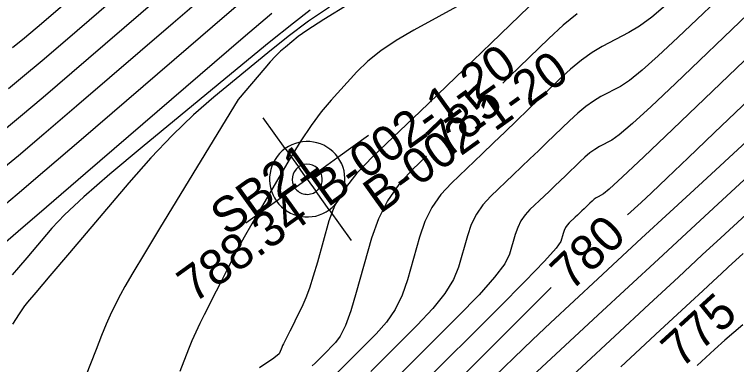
# Model space of a CAD drawing. Extents: x 2079879 to 2092887, y 778083 to 784051.
# Drawn here: x 2084271.8 to 2084329.3, y 781004.3 to 781032.2 of the extents above; entities that cross this region are included whole.
import ezdxf

# ---------------------------------------------------------------- set-up
doc = ezdxf.new("R2010")
doc.units = 0
for name, color, linetype in [('DT_X_Contour_Major', 7, 'Continuous'), ('DT_X_Contour_Minor', 7, 'Continuous'), ('GT_Instrumented_Soil_Boring', 7, 'Continuous'), ('GT_Project_Text', 7, 'Continuous'), ('SV_X_Text_Comment', 7, 'Continuous'), ('SV_X_Text_Elevation', 7, 'Continuous'), ('SV_X_Text_Name', 7, 'Continuous')]:
    doc.layers.add(name, color=color, linetype=linetype)

msp = doc.modelspace()

# ---------------------------------------------------------------- linework, layer by layer
at = {"layer": 'DT_X_Contour_Major'}
for points in [[(2084360.852, 781055.872), (2084359.712, 781054.727), (2084359.083, 781054.086), (2084358.088, 781053.046), (2084357.445, 781052.385), (2084356.264, 781051.182), (2084354.543, 781049.435), (2084352.284, 781047.146), (2084345.54, 781040.319), (2084343.285, 781038.038), (2084341.579, 781036.315), (2084340.42, 781035.151), (2084339.81, 781034.546), (2084338.913, 781033.675), (2084338.331, 781033.114), (2084337.258, 781032.085), (2084335.693, 781030.587), (2084333.638, 781028.621), (2084327.502, 781022.753), (2084325.413, 781020.757), (2084323.746, 781019.17), (2084322.501, 781017.992), (2084321.679, 781017.224), (2084320.608, 781016.237)], [(2084281.986, 781035.329), (2084276.04, 781030.211), (2084274.032, 781028.491), (2084272.466, 781027.169), (2084271.345, 781026.244)], [(2084295.339, 781032.514), (2084294.017, 781031.482), (2084292.089, 781029.927), (2084289.553, 781027.851), (2084281.982, 781021.617), (2084279.404, 781019.461), (2084277.35, 781017.67), (2084275.817, 781016.242), (2084274.808, 781015.179), (2084272.814, 781012.828), (2084272.148, 781012.049), (2084271.647, 781011.475)], [(2084316.594, 781032.221), (2084315.485, 781031.315), (2084314.336, 781030.258), (2084311.218, 781027.241), (2084310.668, 781026.71)], [(2084304.6, 781020.901), (2084303.469, 781019.823), (2084302.397, 781018.654), (2084301.502, 781017.356), (2084300.782, 781015.929), (2084300.238, 781014.374), (2084299.023, 781010.054), (2084298.577, 781008.59), (2084298.153, 781007.439), (2084297.749, 781006.599), (2084297.366, 781006.071), (2084296.372, 781005.08), (2084296.027, 781004.737), (2084295.736, 781004.45), (2084295.499, 781004.22)], [(2084314.526, 781010.444), (2084313.966, 781009.888), (2084311.739, 781007.669), (2084305.072, 781001.02)]]:
    msp.add_lwpolyline(points, dxfattribs=at)
at = {"layer": 'DT_X_Contour_Minor'}
for points in [[(2084329.18, 781034.706), (2084324.612, 781030.338), (2084323.041, 781028.866), (2084321.753, 781027.727), (2084320.748, 781026.921), (2084320.026, 781026.448), (2084318.479, 781025.631), (2084317.888, 781025.281), (2084317.272, 781024.846), (2084316.634, 781024.323), (2084315.972, 781023.715), (2084314.177, 781021.978), (2084313.504, 781021.328), (2084312.833, 781020.683), (2084312.163, 781020.041), (2084311.495, 781019.403), (2084309.715, 781017.706), (2084309.098, 781017.033), (2084308.582, 781016.286), (2084308.168, 781015.464), (2084307.855, 781014.569), (2084307.155, 781012.081), (2084306.752, 781011.093), (2084306.069, 781009.992), (2084305.106, 781008.78), (2084303.862, 781007.456), (2084300.172, 781003.775)], [(2084290.705, 781033.872), (2084288.536, 781032.006), (2084285.676, 781029.544), (2084277.124, 781022.185), (2084274.251, 781019.722), (2084272.042, 781017.85), (2084270.5, 781016.571)], [(2084287.054, 781033.717), (2084284.446, 781031.472), (2084276.763, 781024.861), (2084274.168, 781022.638), (2084272.146, 781020.929), (2084270.696, 781019.735)], [(2084283.216, 781033.4), (2084276.401, 781027.536), (2084274.1, 781025.565), (2084272.306, 781024.049), (2084271.02, 781022.99)], [(2084298.426, 781032.995), (2084296.434, 781031.76), (2084295.088, 781030.895), (2084294.389, 781030.4), (2084293.387, 781029.575), (2084293.002, 781029.238), (2084292.597, 781028.845), (2084292.174, 781028.396), (2084291.732, 781027.892), (2084289.624, 781025.407), (2084283.37, 781015.14), (2084282.17, 781013.161), (2084281.251, 781011.628), (2084280.613, 781010.538), (2084280.256, 781009.893), (2084279.678, 781008.764), (2084279.43, 781008.245), (2084279.12, 781007.534), (2084278.747, 781006.631), (2084278.312, 781005.537), (2084277.07, 781002.364)], [(2084307.579, 781033.102), (2084303.597, 781030.923), (2084302.194, 781030.102), (2084300.972, 781029.274), (2084299.931, 781028.439), (2084299.071, 781027.597), (2084297.019, 781025.343), (2084296.238, 781024.42), (2084295.435, 781023.344), (2084294.61, 781022.115), (2084293.763, 781020.731), (2084291.474, 781016.836), (2084290.701, 781015.514), (2084290.1, 781014.47), (2084289.67, 781013.703), (2084289.411, 781013.214), (2084288.95, 781012.281), (2084288.753, 781011.886), (2084288.51, 781011.403), (2084288.219, 781010.83), (2084287.881, 781010.169), (2084286.917, 781008.287), (2084286.568, 781007.587), (2084286.245, 781006.897), (2084285.947, 781006.217), (2084285.674, 781005.548), (2084284.981, 781003.777)], [(2084313.518, 781033.53), (2084309.738, 781029.873), (2084308.322, 781028.505), (2084306.909, 781027.146), (2084305.5, 781025.795), (2084304.093, 781024.452), (2084300.346, 781020.881), (2084299.073, 781019.556), (2084298.065, 781018.26), (2084297.323, 781016.992), (2084296.845, 781015.752), (2084295.926, 781012.483), (2084295.594, 781011.35), (2084295.289, 781010.403), (2084295.011, 781009.642), (2084294.759, 781009.066), (2084294.123, 781007.78), (2084293.905, 781007.339), (2084293.728, 781006.982), (2084293.591, 781006.709), (2084293.495, 781006.521), (2084293.295, 781006.129), (2084293.222, 781005.983), (2084293.155, 781005.839), (2084293.093, 781005.698), (2084293.036, 781005.558), (2084292.891, 781005.189), (2084292.469, 781004.838), (2084291.312, 781004.059)], [(2084275.678, 781032.887), (2084273.963, 781031.418), (2084272.627, 781030.289), (2084271.669, 781029.499)], [(2084296.883, 781032.755), (2084295.225, 781031.621), (2084293.588, 781030.411), (2084291.971, 781029.126), (2084287.684, 781025.596), (2084286.056, 781024.177), (2084284.387, 781022.566), (2084282.677, 781020.764), (2084280.925, 781018.771), (2084276.198, 781013.201), (2084274.647, 781011.372), (2084273.537, 781010.065), (2084272.869, 781009.28), (2084272.643, 781009.015), (2084272.628, 781009.005), (2084272.519, 781008.842), (2084272.201, 781008.358), (2084271.676, 781007.554)], [(2084323.614, 781032.875), (2084322.525, 781031.961), (2084321.554, 781031.245), (2084320.701, 781030.726), (2084318.584, 781029.608), (2084317.775, 781029.13), (2084316.933, 781028.533), (2084316.06, 781027.819), (2084315.154, 781026.987), (2084312.697, 781024.609), (2084311.777, 781023.721), (2084310.859, 781022.837), (2084309.942, 781021.959), (2084309.028, 781021.086), (2084306.592, 781018.765), (2084305.748, 781017.844), (2084305.042, 781016.821), (2084304.475, 781015.697), (2084304.047, 781014.471), (2084303.089, 781011.068), (2084302.665, 781009.841), (2084302.111, 781008.715), (2084301.427, 781007.689), (2084300.614, 781006.763), (2084298.272, 781004.428), (2084297.458, 781003.618)], [(2084292.293, 781032.252), (2084290.019, 781030.295), (2084277.486, 781019.51), (2084274.381, 781016.839), (2084272.13, 781014.908), (2084270.733, 781013.716)], [(2084330.164, 781032.198), (2084324.404, 781026.689), (2084322.468, 781024.857), (2084320.981, 781023.493), (2084319.942, 781022.598), (2084319.351, 781022.17), (2084318.374, 781021.654), (2084318, 781021.433), (2084317.612, 781021.158), (2084317.209, 781020.828), (2084316.791, 781020.444), (2084315.656, 781019.346), (2084315.232, 781018.936), (2084314.808, 781018.528), (2084314.385, 781018.123), (2084313.962, 781017.72), (2084312.838, 781016.648), (2084312.448, 781016.223), (2084312.122, 781015.751), (2084311.861, 781015.232), (2084311.663, 781014.666), (2084311.221, 781013.095), (2084310.84, 781012.344), (2084310.027, 781011.269), (2084308.784, 781009.87), (2084307.111, 781008.148), (2084302.072, 781003.123)], [(2084331.148, 781029.689), (2084324.196, 781023.04), (2084321.896, 781020.848), (2084320.209, 781019.26), (2084319.136, 781018.274), (2084318.677, 781017.892), (2084318.269, 781017.677), (2084318.113, 781017.585), (2084317.951, 781017.47), (2084317.783, 781017.332), (2084317.609, 781017.172), (2084317.136, 781016.715), (2084316.959, 781016.544), (2084316.782, 781016.373), (2084316.606, 781016.204), (2084316.43, 781016.036), (2084315.961, 781015.59), (2084315.799, 781015.412), (2084315.663, 781015.216), (2084315.554, 781014.999), (2084315.471, 781014.763), (2084315.287, 781014.108), (2084314.927, 781013.595), (2084313.986, 781012.546), (2084312.463, 781010.961), (2084310.359, 781008.84), (2084303.972, 781002.471)], [(2084333.905, 781025.614), (2084326.558, 781018.838), (2084323.97, 781016.45), (2084321.719, 781014.371), (2084319.804, 781012.599), (2084318.224, 781011.135), (2084314.46, 781007.641), (2084313.025, 781006.295), (2084311.542, 781004.877), (2084310.012, 781003.387)], [(2084332.978, 781021.872), (2084327.429, 781016.754), (2084325.295, 781014.784), (2084323.053, 781012.711), (2084320.704, 781010.535), (2084318.248, 781008.257), (2084311.554, 781002.043)], [(2084331.387, 781017.518), (2084328.016, 781014.409), (2084326.541, 781013.046), (2084324.643, 781011.29), (2084322.324, 781009.139), (2084319.582, 781006.595), (2084311.707, 780999.285)], [(2084329.797, 781013.165), (2084328.603, 781012.064), (2084328.081, 781011.582), (2084327.409, 781010.96), (2084326.588, 781010.199), (2084325.617, 781009.298), (2084322.83, 781006.71), (2084321.614, 781005.585), (2084320.058, 781004.152)], [(2084329.765, 781007.488), (2084328.352, 781006.26), (2084327.53, 781005.529), (2084326.127, 781004.258)]]:
    msp.add_lwpolyline(points, dxfattribs=at)
at = {"layer": 'GT_Instrumented_Soil_Boring'}
for p, q in [((2084293.369, 781021.501), (2084291.622, 781023.94)), ((2084297.555, 781020.81), (2084299.994, 781022.558)), ((2084293.369, 781021.501), (2084294.418, 781020.038)), ((2084296.092, 781019.762), (2084297.555, 781020.81)), ((2084295.117, 781019.063), (2084294.418, 781020.038)), ((2084295.117, 781019.063), (2084296.092, 781019.762)), ((2084295.117, 781019.063), (2084294.141, 781018.364)), ((2084295.117, 781019.063), (2084295.816, 781018.087)), ((2084294.141, 781018.364), (2084292.678, 781017.315)), ((2084296.864, 781016.624), (2084295.816, 781018.087)), ((2084292.678, 781017.315), (2084290.24, 781015.568)), ((2084296.864, 781016.624), (2084298.612, 781014.186))]:
    msp.add_line(p, q, dxfattribs=at)
for radius, start, end in [(3, 35.62538, 125.62538), (3, 125.62538, 215.62538), (3, 305.62538, 35.62538), (1.2, 125.62538, 215.62538), (1.2, 35.62538, 125.62538), (1.2, 305.62538, 35.62538), (1.2, 215.62538, 305.62538), (3, 215.62538, 305.62538)]:
    msp.add_arc((2084295.117, 781019.063), radius, start, end, dxfattribs=at)

# ---------------------------------------------------------------- texts
at = {"layer": 'DT_X_Contour_Major'}
for s, rotation, p in [('785', 43.7522, (2084306.323, 781020.601)), ('780', 43.60776, (2084316.112, 781010.106)), ('775', 42.32175, (2084324.872, 781003.949))]:
    msp.add_text(s, height=2.8, rotation=rotation, dxfattribs=at).set_placement(p)
at = {"layer": 'GT_Project_Text'}
msp.add_text('B-002-1-20', height=2.8, rotation=35.62538, dxfattribs=at).set_placement((2084300.899, 781016.261))
at = {"layer": 'SV_X_Text_Comment'}
msp.add_text('B-002-1-20', height=2.8, rotation=35.62538, dxfattribs=at).set_placement((2084296.748, 781016.787))
at = {"layer": 'SV_X_Text_Elevation'}
msp.add_text('788.34', height=2.8, rotation=35.62538, dxfattribs=at).set_placement((2084286.103, 781009.159))
at = {"layer": 'SV_X_Text_Name'}
msp.add_text('SB21', height=2.8, rotation=35.62538, dxfattribs=at).set_placement((2084288.737, 781014.491))

doc.saveas('drawing.dxf')
